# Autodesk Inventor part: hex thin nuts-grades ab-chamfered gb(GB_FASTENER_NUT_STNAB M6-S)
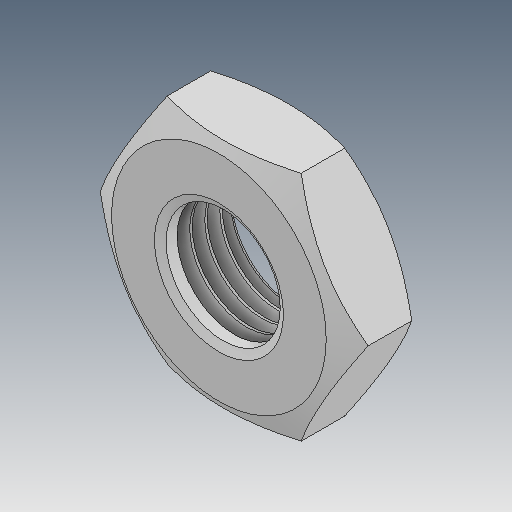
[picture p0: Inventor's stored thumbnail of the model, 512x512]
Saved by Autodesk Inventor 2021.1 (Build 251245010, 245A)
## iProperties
Created: 2019-04
Part Number: hex thin nuts-grades ab-chamfered gb(GB_FASTENER_NUT_STNAB M6-S)
Material: Ogólny
Document SubType Name: Modeling
Designer: user
Density: 1 g/cm^3
Appearance: Domyślna
Author: user
Revision Number: ÈÎºÎ
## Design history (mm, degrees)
feature "ÊäÈë1"
node "Bryła1"
